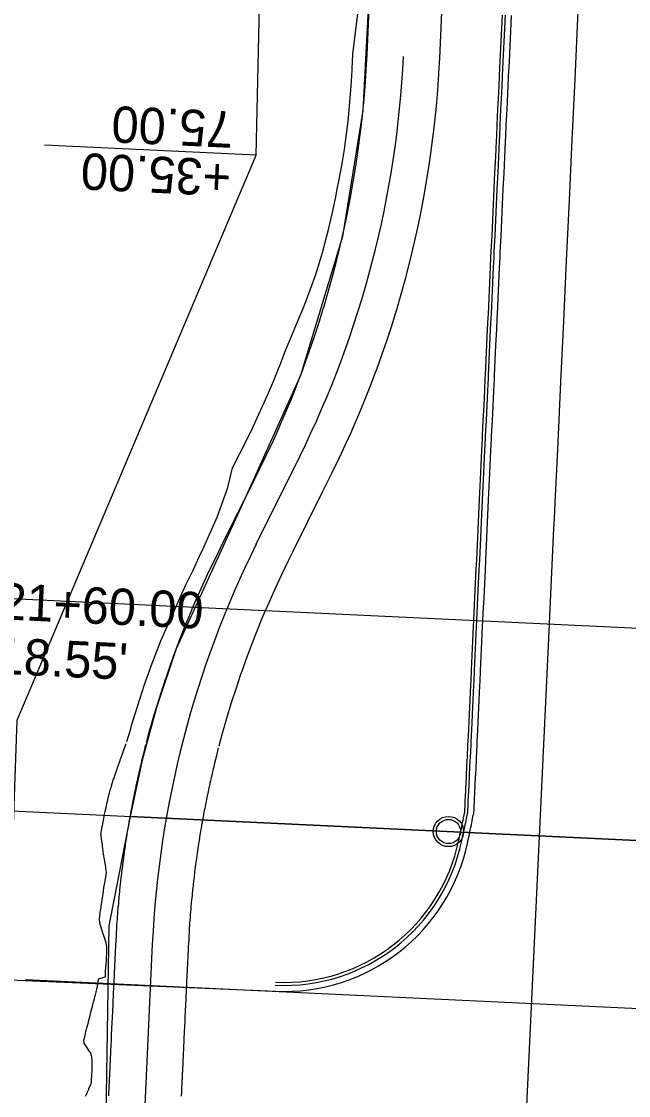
# Model space of a CAD drawing. Extents: x -70 to 701944, y -4 to 666871.
# Drawn here: x 668199.2 to 668299.4, y 655327.1 to 655504.3 of the extents above; entities that cross this region are included whole.
import ezdxf

# ---------------------------------------------------------------- set-up
doc = ezdxf.new("R2010")
doc.units = 0
for name, color, linetype in [('R_Detour', 7, 'Continuous'), ('R_Draft', 7, 'Continuous'), ('R_Drive', 7, 'Continuous'), ('R_No Plot', 7, 'Continuous'), ('R_Proposed Const Limits', 7, 'Continuous'), ('R_Proposed Road', 7, 'Continuous'), ('R_ROW', 7, 'Continuous'), ('R_Striping', 7, 'Continuous'), ('R_Temp Easement Annot', 7, 'Continuous'), ('R_Water', 7, 'Continuous')]:
    doc.layers.add(name, color=color, linetype=linetype)

msp = doc.modelspace()

# ---------------------------------------------------------------- linework, layer by layer
at = {"layer": 'R_Detour'}
msp.add_line((668166.99, 655375.48), (668307.66, 655368.84), dxfattribs=at)
at = {"layer": 'R_Draft'}
msp.add_line((668190.89, 655409.39), (668309.31, 655403.8), dxfattribs=at)
at = {"layer": 'R_Drive'}
msp.add_line((668197.14, 655346.14), (668241.18, 655344.27), dxfattribs=at)
at = {"layer": 'R_No Plot'}
for p, q in [((668237.9, 655418.04), (668245.1, 655432.54)), ((668220.77, 655352.06), (668216.87, 655269.44)), ((668199.86, 655346.22), (668392.43, 655337.13))]:
    msp.add_line(p, q, dxfattribs=at)
for points in [[(668325, 655543.22), (668258.48, 655546.36), (668255.55, 655489.61), (668252.15, 655468.82), (668245.23, 655445.88), (668235.69, 655424.8), (668224.72, 655400.76), (668221.46, 655391.12), (668219.08, 655382.39), (668217.13, 655373.11), (668307.66, 655368.84), (668317.09, 655377.71), (668318.34, 655403.38)], [(668217.12, 655373.11), (668213.57, 655355.07), (668212.94, 655313.25), (668210.91, 655248.27), (668292.71, 655244.41), (668293.73, 655264.72), (668302.84, 655266.71), (668307.66, 655368.84)]]:
    msp.add_lwpolyline(points, close=True, dxfattribs=at)
msp.add_circle((668269.66, 655370.64), 2.5, dxfattribs=at)
for centre, start, end in [((668096.41, 655506.35), 333.6007, 357.2978), ((668386.59, 655344.23), 153.6007, 177.2978)]:
    msp.add_arc(centre, 166, start, end, dxfattribs=at)
at = {"layer": 'R_Proposed Const Limits'}
for points in [[(668216.56, 655385.48), (668216.57, 655385.48), (668217.21, 655387.6), (668217.36, 655388.12), (668217.93, 655390.05), (668218.69, 655392.49), (668219.49, 655394.91), (668220.34, 655397.32), (668220.58, 655397.98), (668221.23, 655399.71), (668222.16, 655402.1), (668223.22, 655404.46), (668224.28, 655406.81), (668224.71, 655407.8), (668225.31, 655409.15), (668226.38, 655411.47), (668227.49, 655413.78), (668228.57, 655416.07), (668229.26, 655417.59), (668231.46, 655422.49), (668233.24, 655427.42), (668234.03, 655430.65), (668235.21, 655433.02), (668236.41, 655435.4), (668237.31, 655437.23), (668237.58, 655437.8), (668238.7, 655440.21), (668239.78, 655442.65), (668240.82, 655445.09), (668241.61, 655447.04), (668241.82, 655447.55), (668242.77, 655450.03), (668243.82, 655452.51), (668244.87, 655455.01), (668245.63, 655456.86), (668245.88, 655457.51), (668246.85, 655460.03), (668247.77, 655462.56), (668248.55, 655465.1), (668249.02, 655466.72), (668249.27, 655467.66), (668249.91, 655470.23), (668250.51, 655472.8), (668251.06, 655475.39), (668251.3, 655476.62), (668251.55, 655477.98), (668252.04, 655480.57), (668252.48, 655483.18), (668252.83, 655485.79), (668252.93, 655486.55), (668253.14, 655488.41), (668253.4, 655491.03), (668253.6, 655493.65), (668253.76, 655496.28), (668253.77, 655496.52), (668253.87, 655498.92), (668254.83, 655506.49)], [(668209.77, 655326.96), (668209.88, 655327.21), (668209.9, 655327.25), (668209.97, 655327.43), (668210.05, 655327.62), (668210.09, 655327.7), (668210.17, 655327.9), (668210.27, 655328.12), (668210.31, 655328.21), (668210.38, 655328.38), (668210.44, 655328.53), (668210.57, 655328.84), (668210.61, 655328.91), (668210.71, 655329.27), (668210.73, 655329.51), (668210.74, 655329.6), (668210.76, 655329.89), (668210.79, 655330.15), (668210.79, 655330.22), (668210.8, 655330.36), (668210.8, 655330.54), (668210.81, 655330.64), (668210.81, 655330.64), (668210.82, 655330.96), (668210.83, 655331.03), (668210.83, 655331.04), (668210.84, 655331.41), (668210.84, 655331.59), (668210.84, 655331.75), (668210.84, 655331.78), (668210.84, 655332.13), (668210.84, 655332.17), (668210.84, 655332.45), (668210.84, 655332.57), (668210.83, 655332.75), (668210.83, 655332.79), (668210.82, 655333.01), (668210.81, 655333.23), (668210.79, 655333.42), (668210.79, 655333.46), (668210.56, 655334.16), (668210.42, 655334.33), (668210, 655334.93), (668209.82, 655335.28), (668209.5, 655335.72), (668209.49, 655336.25), (668209.56, 655336.52), (668209.74, 655337.23), (668209.77, 655337.36), (668209.99, 655338.22), (668209.99, 655338.23), (668210.04, 655338.41), (668210.22, 655339.12), (668210.26, 655339.27), (668210.46, 655340.05), (668210.53, 655340.34), (668210.7, 655341.02), (668210.81, 655341.43), (668210.95, 655342.02), (668211.09, 655342.56), (668211.11, 655342.64), (668211.21, 655343.04), (668211.3, 655343.38), (668211.38, 655343.71), (668211.48, 655344.1), (668211.5, 655344.15), (668211.68, 655344.89), (668211.7, 655344.97), (668211.73, 655345.19), (668211.83, 655345.81), (668211.87, 655346.1), (668211.9, 655346.31), (668213.03, 655346.65), (668213.06, 655347.29), (668213.06, 655347.41), (668213.07, 655347.56), (668213.12, 655348.28), (668213.13, 655348.51), (668213.14, 655348.55), (668213.14, 655348.59), (668213.2, 655349.49), (668213.22, 655349.79), (668213.22, 655349.84), (668213.25, 655350.5), (668213.27, 655351.02), (668213.28, 655351.15), (668213.29, 655351.54), (668213.13, 655352.29), (668213.09, 655352.42), (668213.07, 655352.5), (668213.03, 655352.63), (668212.72, 655353.59), (668212.67, 655353.74), (668212.62, 655353.88), (668212.31, 655354.88), (668212.3, 655354.91), (668212.27, 655355.01), (668212.18, 655355.28), (668212.03, 655356.04), (668212.06, 655356.25), (668212.12, 655356.69), (668212.19, 655357.21), (668212.24, 655357.56), (668212.24, 655357.59), (668212.31, 655358.1), (668212.34, 655358.32), (668212.35, 655358.4), (668212.43, 655358.95), (668212.52, 655359.52), (668212.53, 655359.61), (668212.6, 655360.08), (668212.64, 655360.32), (668212.72, 655360.85), (668212.73, 655360.96), (668212.85, 655361.71), (668212.92, 655362.1), (668212.97, 655362.42), (668213, 655362.61), (668213.09, 655363.12), (668213.13, 655363.37), (668213.22, 655363.89), (668213.11, 655364.55), (668213.09, 655364.68), (668213.02, 655365.15), (668212.98, 655365.4), (668212.88, 655366), (668212.88, 655366.01), (668212.74, 655366.92), (668212.68, 655367.35), (668212.66, 655367.49), (668212.63, 655367.71), (668212.54, 655368.33), (668212.53, 655368.45), (668212.49, 655368.71), (668212.46, 655368.97), (668212.32, 655369.99), (668212.31, 655370.08), (668212.29, 655370.26), (668212.33, 655370.46), (668212.51, 655371.45), (668212.53, 655371.53), (668212.61, 655371.94), (668212.77, 655372.76), (668212.78, 655372.82), (668212.83, 655373.06), (668212.9, 655373.43), (668213.07, 655374.21), (668213.15, 655374.61), (668213.22, 655374.93), (668213.29, 655375.26), (668213.37, 655375.6), (668213.49, 655376.16), (668213.55, 655376.43), (668213.59, 655376.62), (668213.69, 655377.01), (668213.89, 655377.71), (668213.91, 655377.75), (668213.96, 655377.94), (668214.07, 655378.27), (668214.11, 655378.41), (668214.39, 655379.26), (668214.45, 655379.44), (668214.57, 655379.82), (668214.71, 655380.23), (668214.9, 655380.81), (668214.95, 655380.95), (668215.04, 655381.23), (668215.44, 655382.37), (668215.47, 655382.46), (668215.54, 655382.65), (668215.55, 655382.69), (668215.99, 655383.93), (668216.44, 655385.15)]]:
    msp.add_lwpolyline(points, dxfattribs=at)
at = {"layer": 'R_Proposed Road'}
for points in [[(668219.82, 655385.32), (668219.82, 655385.33), (668220.39, 655387.45), (668220.54, 655387.97), (668221.09, 655389.9), (668221.83, 655392.34), (668222.6, 655394.76), (668223.42, 655397.17), (668223.65, 655397.84), (668224.27, 655399.57), (668225.16, 655401.96), (668226.09, 655404.33), (668227.05, 655406.68), (668227.47, 655407.67), (668228.06, 655409.02), (668229.1, 655411.34), (668230.17, 655413.65), (668231.29, 655415.94), (668232.04, 655417.46), (668234.47, 655422.35), (668236.9, 655427.24), (668238.49, 655430.44), (668239.64, 655432.81), (668240.76, 655435.19), (668241.59, 655437.03), (668241.84, 655437.6), (668242.88, 655440.02), (668243.89, 655442.45), (668244.85, 655444.9), (668245.6, 655446.85), (668245.79, 655447.37), (668246.68, 655449.84), (668247.53, 655452.34), (668248.35, 655454.84), (668248.93, 655456.71), (668249.13, 655457.36), (668249.87, 655459.89), (668250.57, 655462.43), (668251.23, 655464.98), (668251.63, 655466.59), (668251.85, 655467.54), (668252.44, 655470.11), (668252.98, 655472.68), (668253.49, 655475.27), (668253.71, 655476.51), (668253.95, 655477.86), (668254.38, 655480.46), (668254.76, 655483.07), (668255.11, 655485.68), (668255.2, 655486.45), (668255.41, 655488.3), (668255.68, 655490.92), (668255.9, 655493.55), (668256.09, 655496.17), (668256.1, 655496.41), (668256.23, 655498.81), (668256.59, 655506.4)], [(668231.81, 655384.76), (668231.81, 655384.76), (668232.38, 655386.89), (668232.52, 655387.4), (668233.08, 655389.34), (668233.81, 655391.77), (668234.59, 655394.2), (668235.4, 655396.61), (668235.64, 655397.27), (668236.26, 655399.01), (668237.15, 655401.39), (668238.08, 655403.76), (668239.04, 655406.11), (668239.46, 655407.1), (668240.04, 655408.45), (668241.08, 655410.78), (668242.16, 655413.08), (668243.27, 655415.37), (668244.03, 655416.9), (668246.46, 655421.79), (668248.89, 655426.68), (668250.47, 655429.87), (668251.63, 655432.24), (668252.74, 655434.63), (668253.57, 655436.47), (668253.82, 655437.03), (668254.87, 655439.45), (668255.87, 655441.89), (668256.84, 655444.34), (668257.58, 655446.29), (668257.77, 655446.8), (668258.67, 655449.28), (668259.52, 655451.77), (668260.34, 655454.28), (668260.92, 655456.14), (668261.12, 655456.79), (668261.86, 655459.32), (668262.56, 655461.86), (668263.22, 655464.41), (668263.62, 655466.03), (668263.84, 655466.97), (668264.43, 655469.54), (668264.97, 655472.12), (668265.47, 655474.71), (668265.7, 655475.94), (668265.94, 655477.3), (668266.36, 655479.9), (668266.75, 655482.51), (668267.09, 655485.12), (668267.19, 655485.88), (668267.4, 655487.73), (668267.66, 655490.36), (668267.89, 655492.98), (668268.07, 655495.61), (668268.09, 655495.85), (668268.22, 655498.24), (668268.58, 655505.84)], [(668272.78, 655382.82), (668272.78, 655382.83), (668272.88, 655384.98), (668272.91, 655385.5), (668273, 655387.45), (668273.12, 655389.92), (668273.23, 655392.37), (668273.35, 655394.82), (668273.38, 655395.49), (668273.46, 655397.25), (668273.58, 655399.67), (668273.69, 655402.08), (668273.8, 655404.47), (668273.85, 655405.48), (668273.92, 655406.86), (668274.03, 655409.22), (668274.14, 655411.57), (668274.25, 655413.91), (668274.32, 655415.47), (668274.56, 655420.46), (668274.79, 655425.45), (668274.95, 655428.72), (668275.06, 655431.14), (668275.18, 655433.57), (668275.27, 655435.44), (668275.29, 655436.02), (668275.41, 655438.48), (668275.53, 655440.96), (668275.64, 655443.45), (668275.74, 655445.43), (668275.76, 655445.95), (668275.88, 655448.47), (668276, 655450.99), (668276.12, 655453.53), (668276.21, 655455.42), (668276.24, 655456.08), (668276.36, 655458.64), (668276.48, 655461.2), (668276.6, 655463.78), (668276.68, 655465.41), (668276.72, 655466.36), (668276.85, 655468.95), (668276.97, 655471.55), (668277.09, 655474.16), (668277.15, 655475.4), (668277.22, 655476.77), (668277.34, 655479.38), (668277.46, 655482), (668277.59, 655484.62), (668277.62, 655485.39), (668277.71, 655487.25), (668277.83, 655489.88), (668277.96, 655492.51), (668278.08, 655495.14), (668278.09, 655495.38), (668278.21, 655497.77), (668278.57, 655505.37)], [(668273.28, 655382.8), (668273.28, 655382.81), (668273.38, 655384.95), (668273.41, 655385.48), (668273.5, 655387.43), (668273.62, 655389.89), (668273.73, 655392.35), (668273.85, 655394.79), (668273.88, 655395.46), (668273.96, 655397.23), (668274.08, 655399.65), (668274.19, 655402.06), (668274.3, 655404.45), (668274.35, 655405.45), (668274.42, 655406.83), (668274.53, 655409.2), (668274.64, 655411.55), (668274.75, 655413.89), (668274.82, 655415.44), (668275.06, 655420.44), (668275.29, 655425.43), (668275.45, 655428.69), (668275.56, 655431.11), (668275.68, 655433.55), (668275.76, 655435.42), (668275.79, 655435.99), (668275.91, 655438.46), (668276.03, 655440.93), (668276.14, 655443.42), (668276.24, 655445.41), (668276.26, 655445.93), (668276.38, 655448.44), (668276.5, 655450.97), (668276.62, 655453.51), (668276.71, 655455.4), (668276.74, 655456.06), (668276.86, 655458.61), (668276.98, 655461.18), (668277.1, 655463.76), (668277.18, 655465.39), (668277.22, 655466.34), (668277.35, 655468.93), (668277.47, 655471.53), (668277.59, 655474.13), (668277.65, 655475.38), (668277.72, 655476.74), (668277.84, 655479.36), (668277.96, 655481.98), (668278.09, 655484.6), (668278.12, 655485.36), (668278.21, 655487.22), (668278.33, 655489.85), (668278.46, 655492.48), (668278.58, 655495.11), (668278.59, 655495.35), (668278.71, 655497.74), (668279.07, 655505.34)], [(668274.28, 655382.75), (668274.28, 655382.76), (668274.38, 655384.91), (668274.41, 655385.43), (668274.5, 655387.38), (668274.62, 655389.85), (668274.73, 655392.3), (668274.85, 655394.75), (668274.88, 655395.42), (668274.96, 655397.18), (668275.08, 655399.6), (668275.19, 655402.01), (668275.3, 655404.4), (668275.35, 655405.41), (668275.41, 655406.78), (668275.53, 655409.15), (668275.64, 655411.5), (668275.75, 655413.84), (668275.82, 655415.39), (668276.06, 655420.39), (668276.29, 655425.38), (668276.45, 655428.65), (668276.56, 655431.06), (668276.68, 655433.5), (668276.76, 655435.37), (668276.79, 655435.95), (668276.91, 655438.41), (668277.02, 655440.89), (668277.14, 655443.38), (668277.24, 655445.36), (668277.26, 655445.88), (668277.38, 655448.4), (668277.5, 655450.92), (668277.62, 655453.46), (668277.71, 655455.35), (668277.74, 655456.01), (668277.86, 655458.57), (668277.98, 655461.13), (668278.1, 655463.71), (668278.18, 655465.34), (668278.22, 655466.29), (668278.35, 655468.88), (668278.47, 655471.48), (668278.59, 655474.09), (668278.65, 655475.33), (668278.71, 655476.7), (668278.84, 655479.31), (668278.96, 655481.93), (668279.08, 655484.55), (668279.12, 655485.32), (668279.21, 655487.18), (668279.33, 655489.8), (668279.46, 655492.43), (668279.58, 655495.07), (668279.59, 655495.31), (668279.71, 655497.7), (668280.06, 655505.29)], [(668213.59, 655327.04), (668213.59, 655327.08), (668213.6, 655327.26), (668213.61, 655327.45), (668213.61, 655327.53), (668213.62, 655327.73), (668213.63, 655327.97), (668213.63, 655328.05), (668213.64, 655328.23), (668213.65, 655328.38), (668213.66, 655328.69), (668213.67, 655328.77), (668213.68, 655329.13), (668213.7, 655329.37), (668213.7, 655329.46), (668213.71, 655329.75), (668213.73, 655330.01), (668213.73, 655330.08), (668213.74, 655330.22), (668213.74, 655330.4), (668213.75, 655330.5), (668213.75, 655330.5), (668213.76, 655330.82), (668213.77, 655330.89), (668213.77, 655330.9), (668213.79, 655331.27), (668213.79, 655331.45), (668213.8, 655331.61), (668213.8, 655331.64), (668213.82, 655331.99), (668213.82, 655332.03), (668213.84, 655332.31), (668213.84, 655332.43), (668213.85, 655332.6), (668213.85, 655332.65), (668213.86, 655332.86), (668213.87, 655333.08), (668213.88, 655333.28), (668213.88, 655333.31), (668213.92, 655334.01), (668213.92, 655334.17), (668213.95, 655334.74), (668213.97, 655335.09), (668213.99, 655335.51), (668214.01, 655336.04), (668214.02, 655336.31), (668214.06, 655337.02), (668214.06, 655337.15), (668214.1, 655338.03), (668214.11, 655338.04), (668214.11, 655338.22), (668214.15, 655338.94), (668214.15, 655339.09), (668214.19, 655339.88), (668214.21, 655340.16), (668214.24, 655340.85), (668214.26, 655341.27), (668214.29, 655341.86), (668214.31, 655342.4), (668214.32, 655342.48), (668214.33, 655342.9), (668214.35, 655343.23), (668214.37, 655343.57), (668214.38, 655343.96), (668214.39, 655344.02), (668214.42, 655344.76), (668214.43, 655344.84), (668214.44, 655345.06), (668214.47, 655345.69), (668214.48, 655345.97), (668214.49, 655346.18), (668214.51, 655346.58), (668214.54, 655347.22), (668214.54, 655347.34), (668214.55, 655347.49), (668214.59, 655348.21), (668214.6, 655348.44), (668214.6, 655348.48), (668214.6, 655348.52), (668214.64, 655349.42), (668214.66, 655349.72), (668214.66, 655349.77), (668214.69, 655350.43), (668214.72, 655350.96), (668214.72, 655351.09), (668214.74, 655351.47), (668214.77, 655352.21), (668214.78, 655352.34), (668214.78, 655352.42), (668214.79, 655352.54), (668214.84, 655353.49), (668214.85, 655353.64), (668214.85, 655353.78), (668214.91, 655354.76), (668214.91, 655354.79), (668214.92, 655354.88), (668214.94, 655355.15), (668214.99, 655355.9), (668215, 655356.11), (668215.03, 655356.55), (668215.07, 655357.07), (668215.1, 655357.42), (668215.1, 655357.45), (668215.15, 655357.96), (668215.16, 655358.19), (668215.17, 655358.27), (668215.22, 655358.82), (668215.27, 655359.39), (668215.28, 655359.48), (668215.32, 655359.96), (668215.35, 655360.19), (668215.4, 655360.72), (668215.41, 655360.84), (668215.49, 655361.59), (668215.53, 655361.98), (668215.56, 655362.3), (668215.58, 655362.49), (668215.64, 655363), (668215.67, 655363.25), (668215.73, 655363.77), (668215.81, 655364.43), (668215.83, 655364.55), (668215.88, 655365.01), (668215.92, 655365.26), (668215.99, 655365.86), (668216, 655365.87), (668216.12, 655366.76), (668216.18, 655367.18), (668216.2, 655367.32), (668216.23, 655367.54), (668216.32, 655368.15), (668216.33, 655368.27), (668216.37, 655368.52), (668216.41, 655368.78), (668216.57, 655369.79), (668216.58, 655369.88), (668216.61, 655370.05), (668216.64, 655370.26), (668216.8, 655371.24), (668216.82, 655371.32), (668216.89, 655371.74), (668217.03, 655372.56), (668217.04, 655372.62), (668217.08, 655372.86), (668217.15, 655373.23), (668217.29, 655374.01), (668217.37, 655374.41), (668217.43, 655374.73), (668217.49, 655375.07), (668217.56, 655375.41), (668217.67, 655375.96), (668217.72, 655376.24), (668217.76, 655376.42), (668217.84, 655376.81), (668217.98, 655377.51), (668217.99, 655377.56), (668218.03, 655377.75), (668218.1, 655378.07), (668218.13, 655378.22), (668218.32, 655379.07), (668218.36, 655379.26), (668218.44, 655379.64), (668218.53, 655380.05), (668218.67, 655380.64), (668218.7, 655380.78), (668218.77, 655381.06), (668219.04, 655382.2), (668219.06, 655382.29), (668219.1, 655382.48), (668219.11, 655382.53), (668219.42, 655383.76), (668219.73, 655385)], [(668225.6, 655326.97), (668225.61, 655327.17), (668225.62, 655327.4), (668225.62, 655327.49), (668225.63, 655327.66), (668225.64, 655327.81), (668225.65, 655328.12), (668225.65, 655328.2), (668225.67, 655328.56), (668225.68, 655328.8), (668225.69, 655328.89), (668225.7, 655329.19), (668225.71, 655329.44), (668225.72, 655329.51), (668225.72, 655329.66), (668225.73, 655329.83), (668225.74, 655329.93), (668225.74, 655329.93), (668225.75, 655330.26), (668225.75, 655330.32), (668225.76, 655330.34), (668225.77, 655330.7), (668225.78, 655330.88), (668225.79, 655331.04), (668225.79, 655331.07), (668225.81, 655331.42), (668225.81, 655331.46), (668225.82, 655331.74), (668225.83, 655331.86), (668225.84, 655332.04), (668225.84, 655332.08), (668225.85, 655332.3), (668225.86, 655332.52), (668225.87, 655332.71), (668225.87, 655332.74), (668225.9, 655333.44), (668225.91, 655333.6), (668225.94, 655334.17), (668225.95, 655334.52), (668225.97, 655334.94), (668226, 655335.47), (668226.01, 655335.75), (668226.04, 655336.46), (668226.05, 655336.59), (668226.09, 655337.46), (668226.09, 655337.47), (668226.1, 655337.65), (668226.13, 655338.37), (668226.14, 655338.52), (668226.18, 655339.31), (668226.19, 655339.6), (668226.22, 655340.29), (668226.24, 655340.7), (668226.27, 655341.29), (668226.3, 655341.84), (668226.3, 655341.92), (668226.32, 655342.33), (668226.34, 655342.67), (668226.35, 655343), (668226.37, 655343.4), (668226.37, 655343.45), (668226.41, 655344.19), (668226.41, 655344.27), (668226.42, 655344.49), (668226.45, 655345.12), (668226.47, 655345.41), (668226.48, 655345.62), (668226.49, 655346.01), (668226.53, 655346.65), (668226.53, 655346.77), (668226.54, 655346.93), (668226.57, 655347.64), (668226.58, 655347.88), (668226.58, 655347.92), (668226.59, 655347.95), (668226.63, 655348.86), (668226.64, 655349.16), (668226.65, 655349.21), (668226.68, 655349.87), (668226.7, 655350.39), (668226.71, 655350.52), (668226.73, 655350.91), (668226.76, 655351.65), (668226.77, 655351.77), (668226.77, 655351.86), (668226.78, 655351.98), (668226.83, 655352.92), (668226.83, 655353.07), (668226.84, 655353.21), (668226.9, 655354.19), (668226.9, 655354.23), (668226.91, 655354.32), (668226.92, 655354.59), (668226.98, 655355.34), (668226.99, 655355.55), (668227.02, 655355.98), (668227.06, 655356.51), (668227.09, 655356.85), (668227.09, 655356.89), (668227.13, 655357.4), (668227.15, 655357.63), (668227.16, 655357.7), (668227.2, 655358.25), (668227.26, 655358.83), (668227.26, 655358.92), (668227.31, 655359.39), (668227.33, 655359.63), (668227.38, 655360.15), (668227.4, 655360.27), (668227.47, 655361.02), (668227.51, 655361.41), (668227.55, 655361.73), (668227.57, 655361.92), (668227.63, 655362.43), (668227.66, 655362.69), (668227.72, 655363.21), (668227.8, 655363.86), (668227.81, 655363.98), (668227.87, 655364.45), (668227.9, 655364.7), (668227.98, 655365.29), (668227.98, 655365.3), (668228.1, 655366.2), (668228.16, 655366.62), (668228.18, 655366.75), (668228.21, 655366.97), (668228.3, 655367.58), (668228.32, 655367.71), (668228.36, 655367.96), (668228.4, 655368.22), (668228.55, 655369.23), (668228.57, 655369.31), (668228.6, 655369.49), (668228.63, 655369.69), (668228.79, 655370.68), (668228.8, 655370.76), (668228.87, 655371.17), (668229.02, 655372), (668229.03, 655372.06), (668229.07, 655372.3), (668229.14, 655372.67), (668229.28, 655373.44), (668229.35, 655373.84), (668229.41, 655374.17), (668229.48, 655374.5), (668229.54, 655374.84), (668229.65, 655375.39), (668229.71, 655375.67), (668229.75, 655375.85), (668229.82, 655376.24), (668229.97, 655376.95), (668229.98, 655377), (668230.02, 655377.18), (668230.09, 655377.51), (668230.12, 655377.65), (668230.3, 655378.51), (668230.34, 655378.69), (668230.43, 655379.07), (668230.52, 655379.48), (668230.65, 655380.07), (668230.69, 655380.21), (668230.75, 655380.49), (668231.02, 655381.63), (668231.04, 655381.73), (668231.09, 655381.91), (668231.1, 655381.96), (668231.41, 655383.2), (668231.72, 655384.43)], [(668271.37, 655369.17), (668271.54, 655369.99), (668271.56, 655370.05), (668271.61, 655370.29), (668271.68, 655370.66), (668271.84, 655371.43), (668271.93, 655371.83), (668272, 655372.16), (668272.07, 655372.49), (668272.14, 655372.83), (668272.25, 655373.38), (668272.31, 655373.66), (668272.35, 655373.84), (668272.37, 655374.24), (668272.4, 655374.95), (668272.4, 655374.99), (668272.41, 655375.18), (668272.43, 655375.51), (668272.43, 655375.66), (668272.47, 655376.52), (668272.48, 655376.7), (668272.5, 655377.08), (668272.52, 655377.5), (668272.55, 655378.09), (668272.56, 655378.23), (668272.57, 655378.52), (668272.62, 655379.67), (668272.63, 655379.76), (668272.64, 655379.95), (668272.64, 655380), (668272.7, 655381.25), (668272.76, 655382.49), (668272.78, 655382.82)], [(668271.83, 655368.94), (668271.87, 655369.15), (668272.04, 655369.97), (668272.05, 655370.03), (668272.1, 655370.27), (668272.18, 655370.63), (668272.34, 655371.41), (668272.43, 655371.81), (668272.5, 655372.13), (668272.56, 655372.47), (668272.64, 655372.81), (668272.75, 655373.36), (668272.81, 655373.64), (668272.85, 655373.82), (668272.87, 655374.21), (668272.9, 655374.92), (668272.9, 655374.97), (668272.91, 655375.16), (668272.93, 655375.49), (668272.93, 655375.63), (668272.97, 655376.49), (668272.98, 655376.68), (668273, 655377.06), (668273.02, 655377.48), (668273.05, 655378.07), (668273.05, 655378.21), (668273.07, 655378.49), (668273.12, 655379.65), (668273.13, 655379.74), (668273.14, 655379.93), (668273.14, 655379.98), (668273.2, 655381.23), (668273.26, 655382.47), (668273.28, 655382.8)], [(668272.84, 655368.9), (668272.88, 655369.1), (668273.05, 655369.92), (668273.06, 655369.98), (668273.11, 655370.22), (668273.19, 655370.59), (668273.35, 655371.36), (668273.44, 655371.76), (668273.5, 655372.08), (668273.57, 655372.42), (668273.64, 655372.76), (668273.76, 655373.31), (668273.82, 655373.59), (668273.86, 655373.77), (668273.88, 655374.16), (668273.91, 655374.87), (668273.91, 655374.92), (668273.92, 655375.11), (668273.94, 655375.44), (668273.94, 655375.59), (668273.98, 655376.45), (668273.99, 655376.63), (668274.01, 655377.01), (668274.03, 655377.43), (668274.06, 655378.02), (668274.06, 655378.16), (668274.08, 655378.45), (668274.13, 655379.6), (668274.14, 655379.69), (668274.14, 655379.88), (668274.15, 655379.93), (668274.21, 655381.18), (668274.26, 655382.42), (668274.28, 655382.75)]]:
    msp.add_lwpolyline(points, dxfattribs=at)
for radius in [31, 30, 29.5]:
    msp.add_arc((668242.49, 655375.24), radius, 267.2979, 348.1932, dxfattribs=at)
at = {"layer": 'R_ROW'}
msp.add_lwpolyline([(668212.48, 655027.95), (668191.19, 655107.04), (668183.46, 655282.6), (668195.34, 655301.06), (668198.49, 655389.01), (668237.93, 655482.26), (668241.48, 655642.27), (668225.92, 655758.13), (668224.14, 655808.01), (668090.41, 656138.46), (668097.37, 656215.3), (668068.22, 656367.07)], dxfattribs=at)
at = {"layer": 'R_Striping'}
msp.add_line((668271.25, 655085.25), (668286.33, 655404.86), dxfattribs=at)
msp.add_lwpolyline([(668286.33, 655404.9), (668287.07, 655420.69), (668287.15, 655422.26), (668287.27, 655424.87), (668287.74, 655434.86), (668288.21, 655444.85), (668288.68, 655454.84), (668289.16, 655464.83), (668289.63, 655474.82), (668290.1, 655484.81), (668290.57, 655494.8), (668291.04, 655504.79), (668291.51, 655514.78), (668291.98, 655524.77), (668292.46, 655534.76), (668292.93, 655544.75), (668293.4, 655554.73), (668293.87, 655564.72), (668294.34, 655574.71), (668294.81, 655584.7), (668295.28, 655594.69), (668295.75, 655604.52), (668296.51, 655614.33), (668297.28, 655624.3)], dxfattribs=at)
at = {"layer": 'R_Temp Easement Annot'}
msp.add_lwpolyline([(668237.93, 655482.26), (668202.97, 655483.91)], dxfattribs=at)
at = {"layer": 'R_Water'}
msp.add_circle((668269.66, 655370.64), 2, dxfattribs=at)

# ---------------------------------------------------------------- texts
at = {"layer": 'R_No Plot'}
for s, p in [('121+60.00 ', (668190.96, 655405.89)), ("118.55' ", (668190.54, 655396.9))]:
    msp.add_text(s, height=6, rotation=357.2978, dxfattribs=at).set_placement(p)
at = {"layer": 'R_Temp Easement Annot'}
for s, p in [('75.00', (668234.27, 655489.44)), ('+35.00', (668233.89, 655481.45))]:
    msp.add_text(s, height=6, rotation=177.2978, dxfattribs=at).set_placement(p)

doc.saveas('drawing.dxf')
